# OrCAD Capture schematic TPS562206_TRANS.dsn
size B; title: TPS562206, 4.2-V to 17-V input, 2-A Synchronous; rev: 1.0; note: Datasheet: SLUSEZ4     EVM: SLUUCQ4; note: Synchronous Step Down Converter; note: Step-Down Voltage Regulator
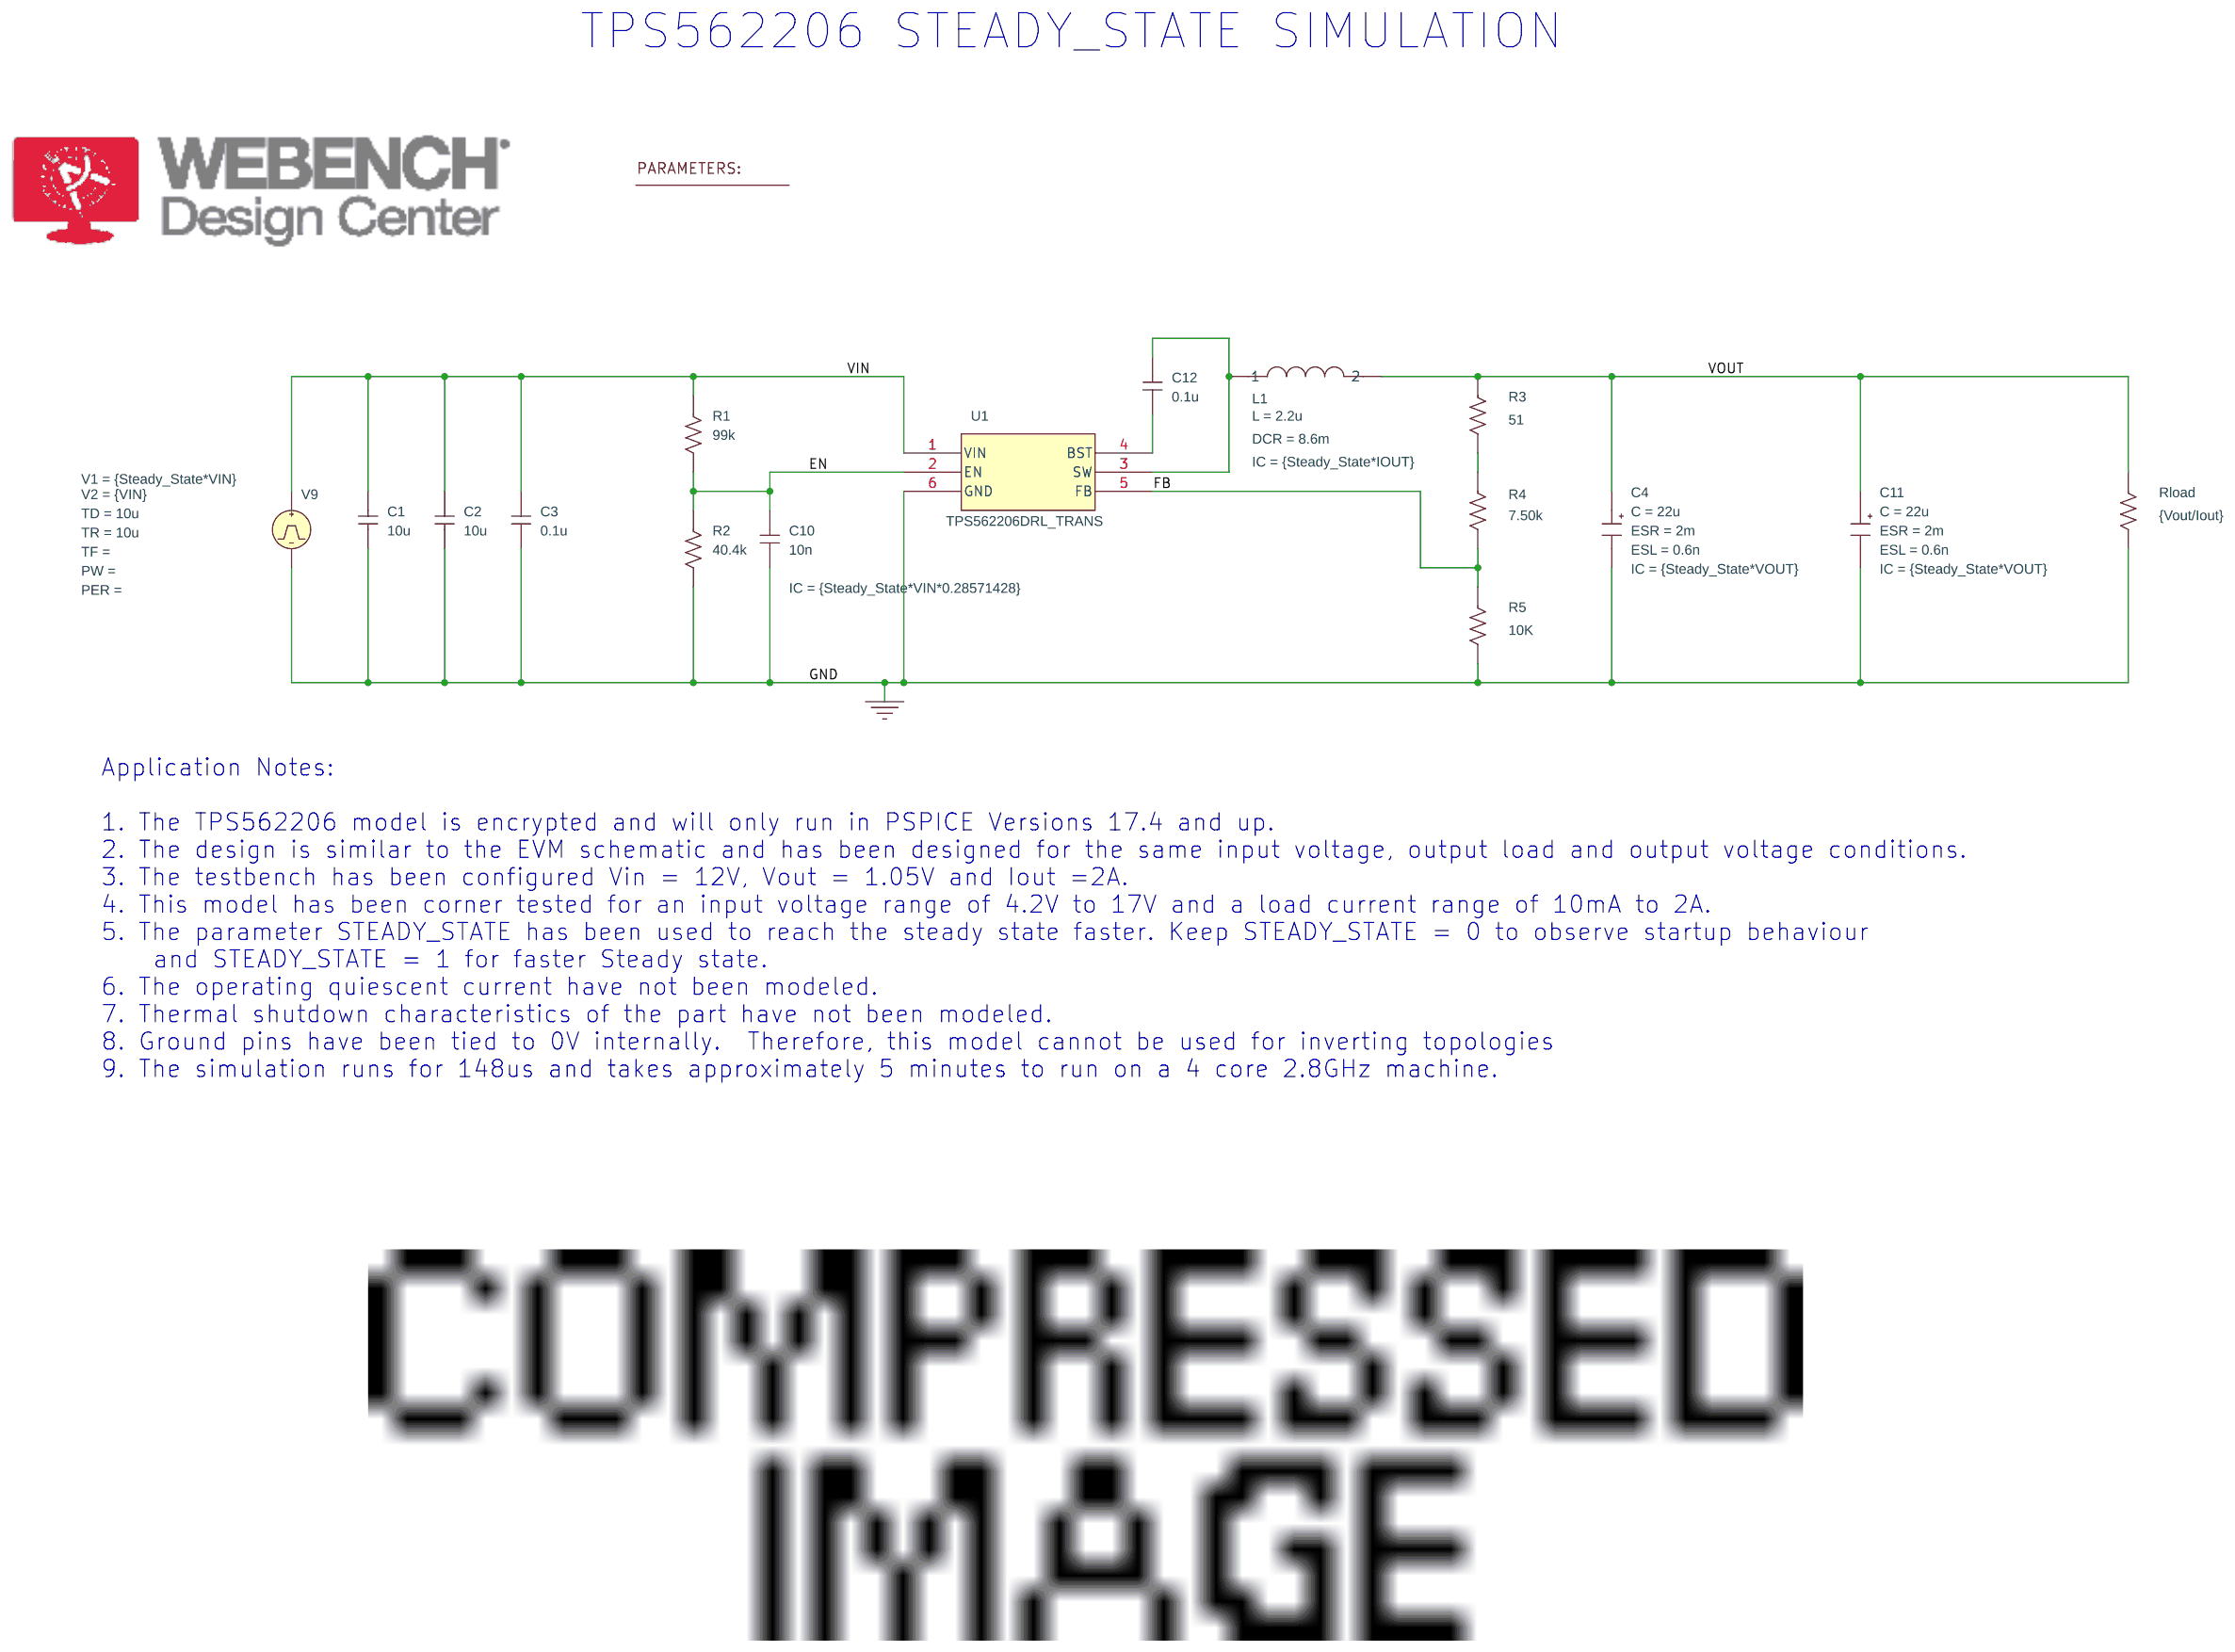
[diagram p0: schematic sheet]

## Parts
3  PARAM
C1  10u  [RAD/CK05]
C2  10u  [RAD/CK05]
C3  0.1u  [RAD/CK05]
C4  CESR
C10  10n  [RAD/CK05]
C11  CESR
C12  0.1u  [RAD/CK05]
L1  LDCR
R1  99k  [AX/RC05]
R2  40.4k  [AX/RC05]
R3  51  [AX/RC05]
R4  7.50k  [AX/RC05]
R5  10K  [AX/RC05]
Rload  {Vout/Iout}  [AX/RC05]
U1  TPS562206DRL_TRANS
V9  VPULSE

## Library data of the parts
3 = PARAM: IOUT: 2; Steady_State: 1; VIN: 12; VOUT: 1.05
C1-C3 = C: IC: {Steady_State*VIN}
C4 C11 = CESR_0: C: 22u; ESL: 0.6n; ESR: 2m; IC: {Steady_State*VOUT}
C10 = C: IC: {Steady_State*VIN*0.28571428}
C12 = C
L1 = LDCR: DCR: 8.6m; IC: {Steady_State*IOUT}; L: 2.2u
R1-R5 Rload = R
U1 = TPS562206_TRANS
V9 = VPULSE: TD: 10u; TR: 10u; V1: {Steady_State*VIN}; V2: {VIN}

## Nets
VIN: C1.1 C2.1 C3.1 R1.1 U1.1(VIN) V9.1(+)
0: C1.2 C2.2 C3.2 C4.2(OUT) C10.2 C11.2(OUT) R2.2 R5.2 Rload.2 U1.6(GND) V9.2(-)
EN: C10.1 R1.2 R2.1 U1.2(EN)
FB: R4.2 R5.1 U1.5(FB)
VOUT: C4.1(IN) C11.1(IN) L1.2 R3.1 Rload.1
N32083: C12.1 L1.1 U1.3(SW)
N32265: C12.2 U1.4(BST)
N32293: R3.2 R4.1

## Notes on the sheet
- TPS562206 STEADY_STATE SIMULATION
- Application Notes:
  1. The TPS562206 model is encrypted and will only run in PSPICE Versions 17.4 and up.
  2. The design is similar to the EVM schematic and has been designed for the same input voltage, output load and output voltage conditions.
  3. The testbench has been configured Vin = 12V, Vout = 1.05V and Iout =2A.
  4. This model has been corner tested for an input voltage range of 4.2V to 17V and a load current range of 10mA to 2A.
  5. The parameter STEADY_STATE has been used to reach the steady state faster. Keep STEADY_STATE = 0 to observe startup behaviour
      and STEADY_STATE = 1 for faster Steady state.
  6. The operating quiescent current have not been modeled.
  7. Thermal shutdown characteristics of the part have not been modeled.
  8. Ground pins have been tied to 0V internally.  Therefore, this model cannot be used for inverting topologies
  9. The simulation runs for 148us and takes approximately 5 minutes to run on a 4 core 2.8GHz machine.
